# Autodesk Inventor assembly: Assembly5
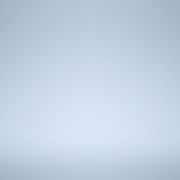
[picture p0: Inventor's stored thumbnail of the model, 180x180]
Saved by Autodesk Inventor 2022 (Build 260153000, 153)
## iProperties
Created: 2024-10
Part Number: Assembly5
Document SubType Name: Assembly
Designer: shimizu
Author: shimizu
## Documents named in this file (1)
- C:\Users\shimizu\Documents\卒論2024\3DCAD\ギアボックス\部品図\Assembly5.iam
